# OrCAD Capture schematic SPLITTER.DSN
size A; title: RF power splitter; rev: 1
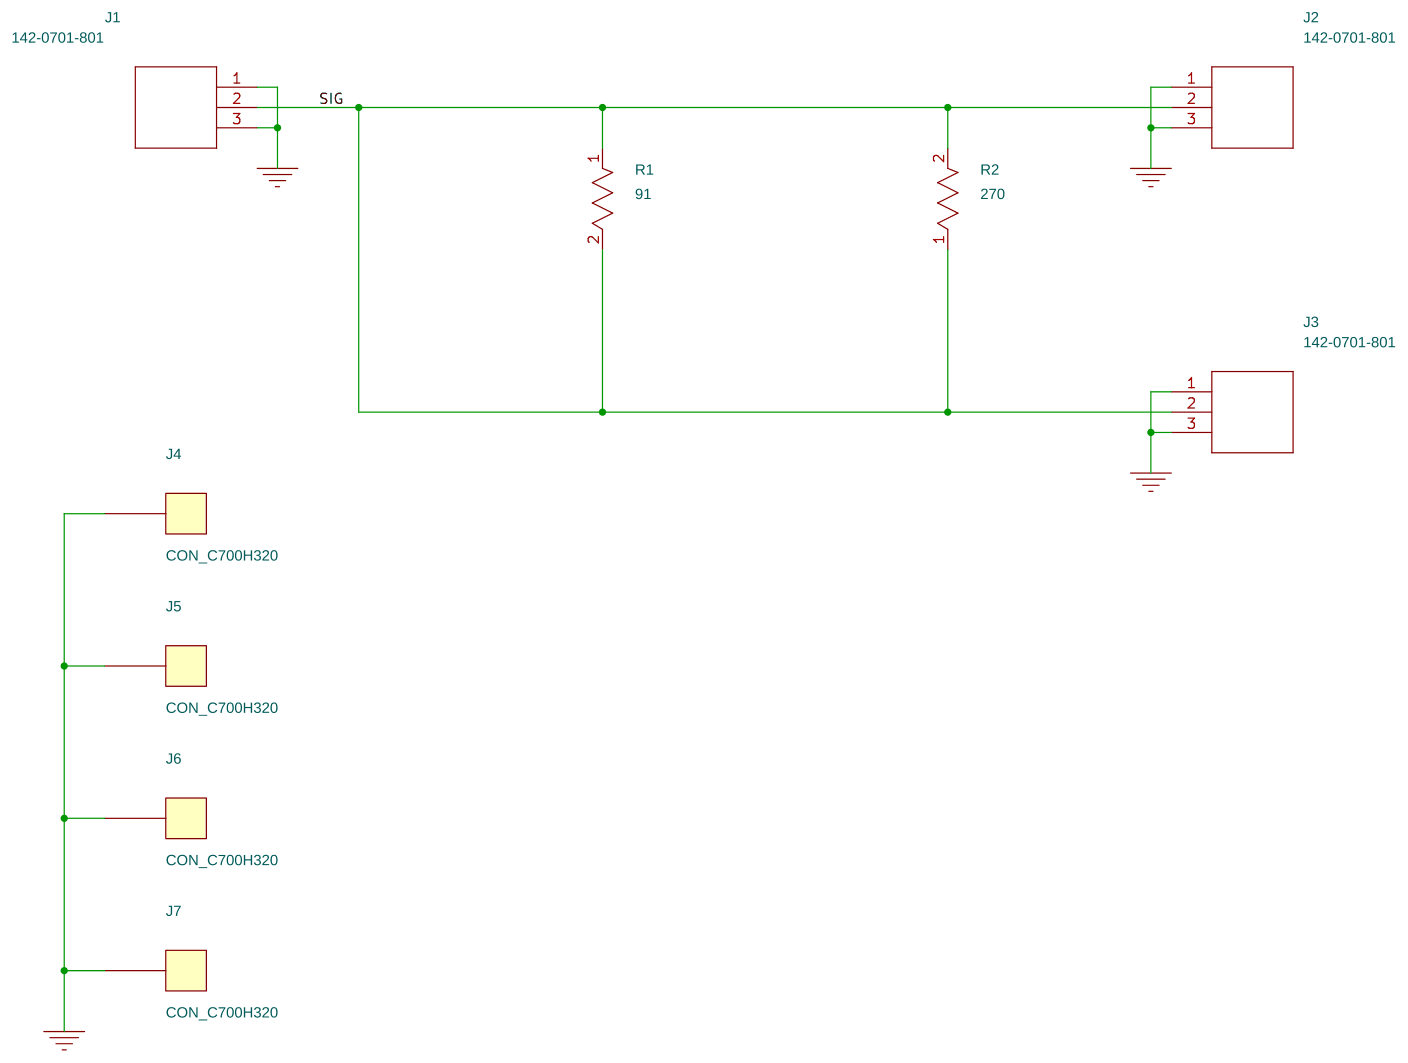
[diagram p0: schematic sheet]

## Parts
J1  142-0701-801  [142-0701-851]
J2  142-0701-801  [142-0701-851]
J3  142-0701-801  [142-0701-851]
J4  CON_C700H320  [CON_C700H320]
J5  CON_C700H320  [CON_C700H320]
J6  CON_C700H320  [CON_C700H320]
J7  CON_C700H320  [CON_C700H320]
R1  91  [R1206]
R2  270  [R1206]

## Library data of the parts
J1-J3 = 142-0701-801: 3D_Image_URL: https://componentsearchengine.com/2D/0/248901.png; Body_Length: 0; Body_Width: 0; Category: Connector; Confidence: C4 - In house written; Height: 0; Manufacturer: Cinch Connectivity Solutions; Package_Category: Other; Pin_Count: 3; Released_Date: 2017-10-22 10:52:14; Source_Version: 1.1; Status: Released
J4-J7 = CON1: CONNECTION PAD ROUND 7.0MM,3.5MM HOLE; CLASS: IO; PART_NUMBER: CON-00000042
R1 = RC0603FR-0791RL: Manufacturer Name: Yageo
R2 = RMCF0603FT270R: Manufacturer Name: Stackpole International

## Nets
GND: J1.1 J1.3 J2.1 J2.3 J3.1 J3.3 J4.1 J5.1 J6.1 J7.1
SIG: J1.2 J2.2 J3.2 R1.1 R1.2 R2.1 R2.2
